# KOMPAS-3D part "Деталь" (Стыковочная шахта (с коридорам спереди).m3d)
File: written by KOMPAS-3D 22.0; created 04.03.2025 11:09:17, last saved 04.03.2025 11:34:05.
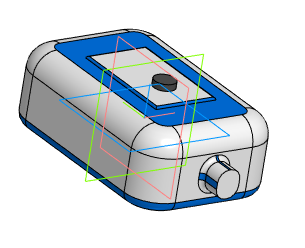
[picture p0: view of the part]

Document properties: Автор: Пользователь Windows; Полное имя файла: C:\Users\Student\Documents\Картошечка\База Сабнатика\Стыковочная шахта\Стыковочная шахта (с коридорам спереди).m3d

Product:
- Body: Тело 1
    Масса: 1.418144
- Part/product: Деталь
    Масса: 1.441343

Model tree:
1. Эскиз:1
2. Элемент выдавливания:1
     Расстояние 1 = 35
3. Скругление:1  (with: Элемент выдавливания:1)
     Радиус = 15
4. Скругление:2  (with: Элемент выдавливания:1)
     Радиус = 10
5. Скругление:3  (with: Элемент выдавливания:1)
     Радиус = 5
6. Эскиз:2  (with: Элемент выдавливания:1)
7. Элемент выдавливания:2
     Расстояние 2 = 12
8. Эскиз:3  (with: Элемент выдавливания:1)
9. Элемент выдавливания:3
     Расстояние 1 = 1
10. Скругление:4  (with: Элемент выдавливания:3)
     Радиус = 1
11. Эскиз:4  (with: Элемент выдавливания:3)
12. Элемент выдавливания:4
     Расстояние 1 = 3
13. Эскиз:7  (with: Элемент выдавливания:1)
14. Элемент выдавливания:7
     Расстояние 1 = 10
15. Скругление:7  (with: Элемент выдавливания:7)
     Радиус = 2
